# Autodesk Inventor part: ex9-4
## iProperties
Author: Administrator
Created: 2001-09
Part Number: ex9-4
Document SubType Name: Sheet Metal
Designer: Administrator
Control State: 0
Master: False
Checked Out: False
PropertySet Name: Design Tracking Control
Length Units: 11272
Angle Units: 11279
Time Units: 11290
Mass Units: 11286
Shininess: 3
Angle Display Precision: 2
Document Length Units: 11272
Document Angle Units: 11286
Document Time Units: 11279
Document Mass Units: 11290
Document Length Units Precision: 3
Document Angle Units Precision: 2
Compacted: False
PropertySet Name: _Private Model Information
Density: 0.0
Volumn: 0.0
Area: 0.0
PropertySet Name: Model Information
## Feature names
1. Plate1
2. Bend1
3. Plate2
4. Bend2
5. Cut1
